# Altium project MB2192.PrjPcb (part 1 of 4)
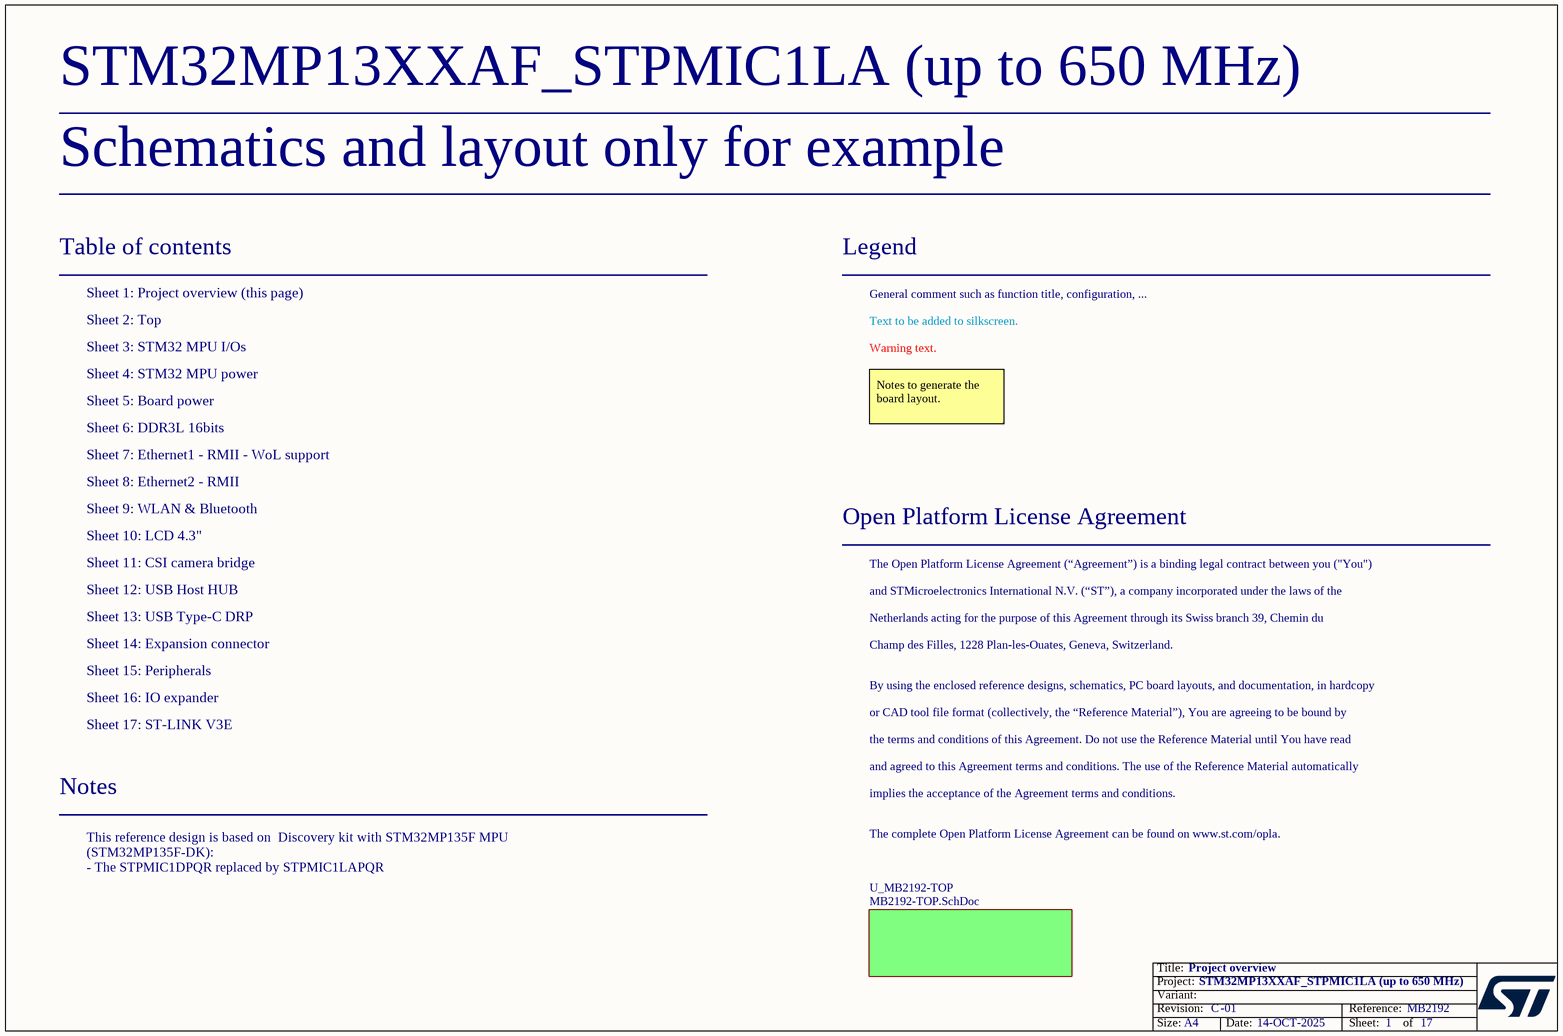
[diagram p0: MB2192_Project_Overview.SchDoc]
Board_Assembly_Revision: 01; Board_Document_Date: 14-OCT-2025; Board_Name: STM32MP13XXAF_STPMIC1LA (up to 650 MHz); Board_PCB_Revision: C; Board_Reference: MB2192
17 sheets, 567 parts. Net scope: flat (ports and power ports of the same name join across sheets).
Board file: MB2192.PcbDoc
Sheets:
  MB2192_Project_Overview.SchDoc
    U_MB2192-TOP = MB2192-TOP.SchDoc
      U_Ethernet1 = Ethernet1_RMII.SchDoc
      U_Ethernet2 = Ethernet2_RMII.SchDoc
      U_Power_MPU = Power_MPU.SchDoc
      U_Power_Board = Power_Board.SchDoc
      U_ST_LINK_V3E = ST-Link_V3E.SchDoc
      U_WLAN_BLUETOOTH = WLAN_BLUETOOTH.SchDoc
      U_Expansion_Connector = Expansion_Connector.SchDoc
      U_Peripherals = Peripherals.SchDoc
      U_MP135_11x11 = MP135_11x11.SchDoc
      U_LTDC = LCD4.3.SchDoc
      U_IO_Expander = MCP_IO_expander.SchDoc
      U_USB_Host = USB_Host_Hub.SchDoc
      U_CSI_DCMI = CSI_Camera_Bridge.SchDoc
      U_DDR = DDR3L_16bits.SchDoc
      U_USB_TypeC_DRP = USB_TypeC_DRP.SchDoc

## Sheet MB2192_Project_Overview.SchDoc: Project overview
size A4; Date: Not used; ApprovedBy: Not used; CheckedBy: Not used; Author: Not used; CompanyName: STMicroelectronics; DrawnBy: Not used; Engineer: Not used; Organization: Not used; Address1: Not used; Address2: Not used; Address3: Not used; Address4: Not used; DocumentNumber: 1; Revision: Not used; SheetNumber: 1; SheetTotal: 17

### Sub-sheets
U_MB2192-TOP = MB2192-TOP.SchDoc: no entries

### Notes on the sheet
- Schematics and layout only for example
- Table of contents
- Sheet 1: Project overview (this page)
- Legend
- General comment such as function title, configuration, ...
- Sheet 2: Top
- Sheet 3: STM32 MPU I/Os
- Sheet 4: STM32 MPU power
- Text to be added to silkscreen.
- Warning text.
- Sheet 6: DDR3L 16bits
- Sheet 5: Board power
- Notes to generate the board layout.
- Sheet 7: Ethernet1 - RMII - WoL support
- Sheet 8: Ethernet2 - RMII
- Sheet 9: WLAN & Bluetooth
- Sheet 10: LCD 4.3"
- Sheet 11: CSI camera bridge
- Open Platform License Agreement
- The Open Platform License Agreement (“Agreement”) is a binding legal contract between you ("You")
- Sheet 13: USB Type-C DRP
- Sheet 12: USB Host HUB
- Sheet 14: Expansion connector
- and STMicroelectronics International N.V. (“ST”), a company incorporated under the laws of the
- Netherlands acting for the purpose of this Agreement through its Swiss branch 39, Chemin du
- Champ des Filles, 1228 Plan-les-Ouates, Geneva, Switzerland.
- Sheet 15: Peripherals
- Sheet 16: IO expander
- By using the enclosed reference designs, schematics, PC board layouts, and documentation, in hardcopy
- or CAD tool file format (collectively, the “Reference Material”), You are agreeing to be bound by
- Sheet 17: ST-LINK V3E
- the terms and conditions of this Agreement. Do not use the Reference Material until You have read
- and agreed to this Agreement terms and conditions. The use of the Reference Material automatically
- Notes
- implies the acceptance of the Agreement terms and conditions.
- The complete Open Platform License Agreement can be found on www.st.com/opla.
- This reference design is based on  Discovery kit with STM32MP135F MPU (STM32MP135F-DK):
  - The STPMIC1DPQR replaced by STPMIC1LAPQR
  - It is applicable to STM32MP13xA and STM32MP13xC (CPU freq up to 650 MHz)

## Sheet MB2192-TOP.SchDoc: TOP
size A3; Date: Not used; ApprovedBy: Not used; CheckedBy: Not used; Author: Not used; CompanyName: STMicroelectronics; DrawnBy: Not used; Engineer: Not used; Organization: Not used; Address1: Not used; Address2: Not used; Address3: Not used; Address4: Not used; DocumentNumber: 2; Revision: Not used; SheetNumber: 2; SheetTotal: 17
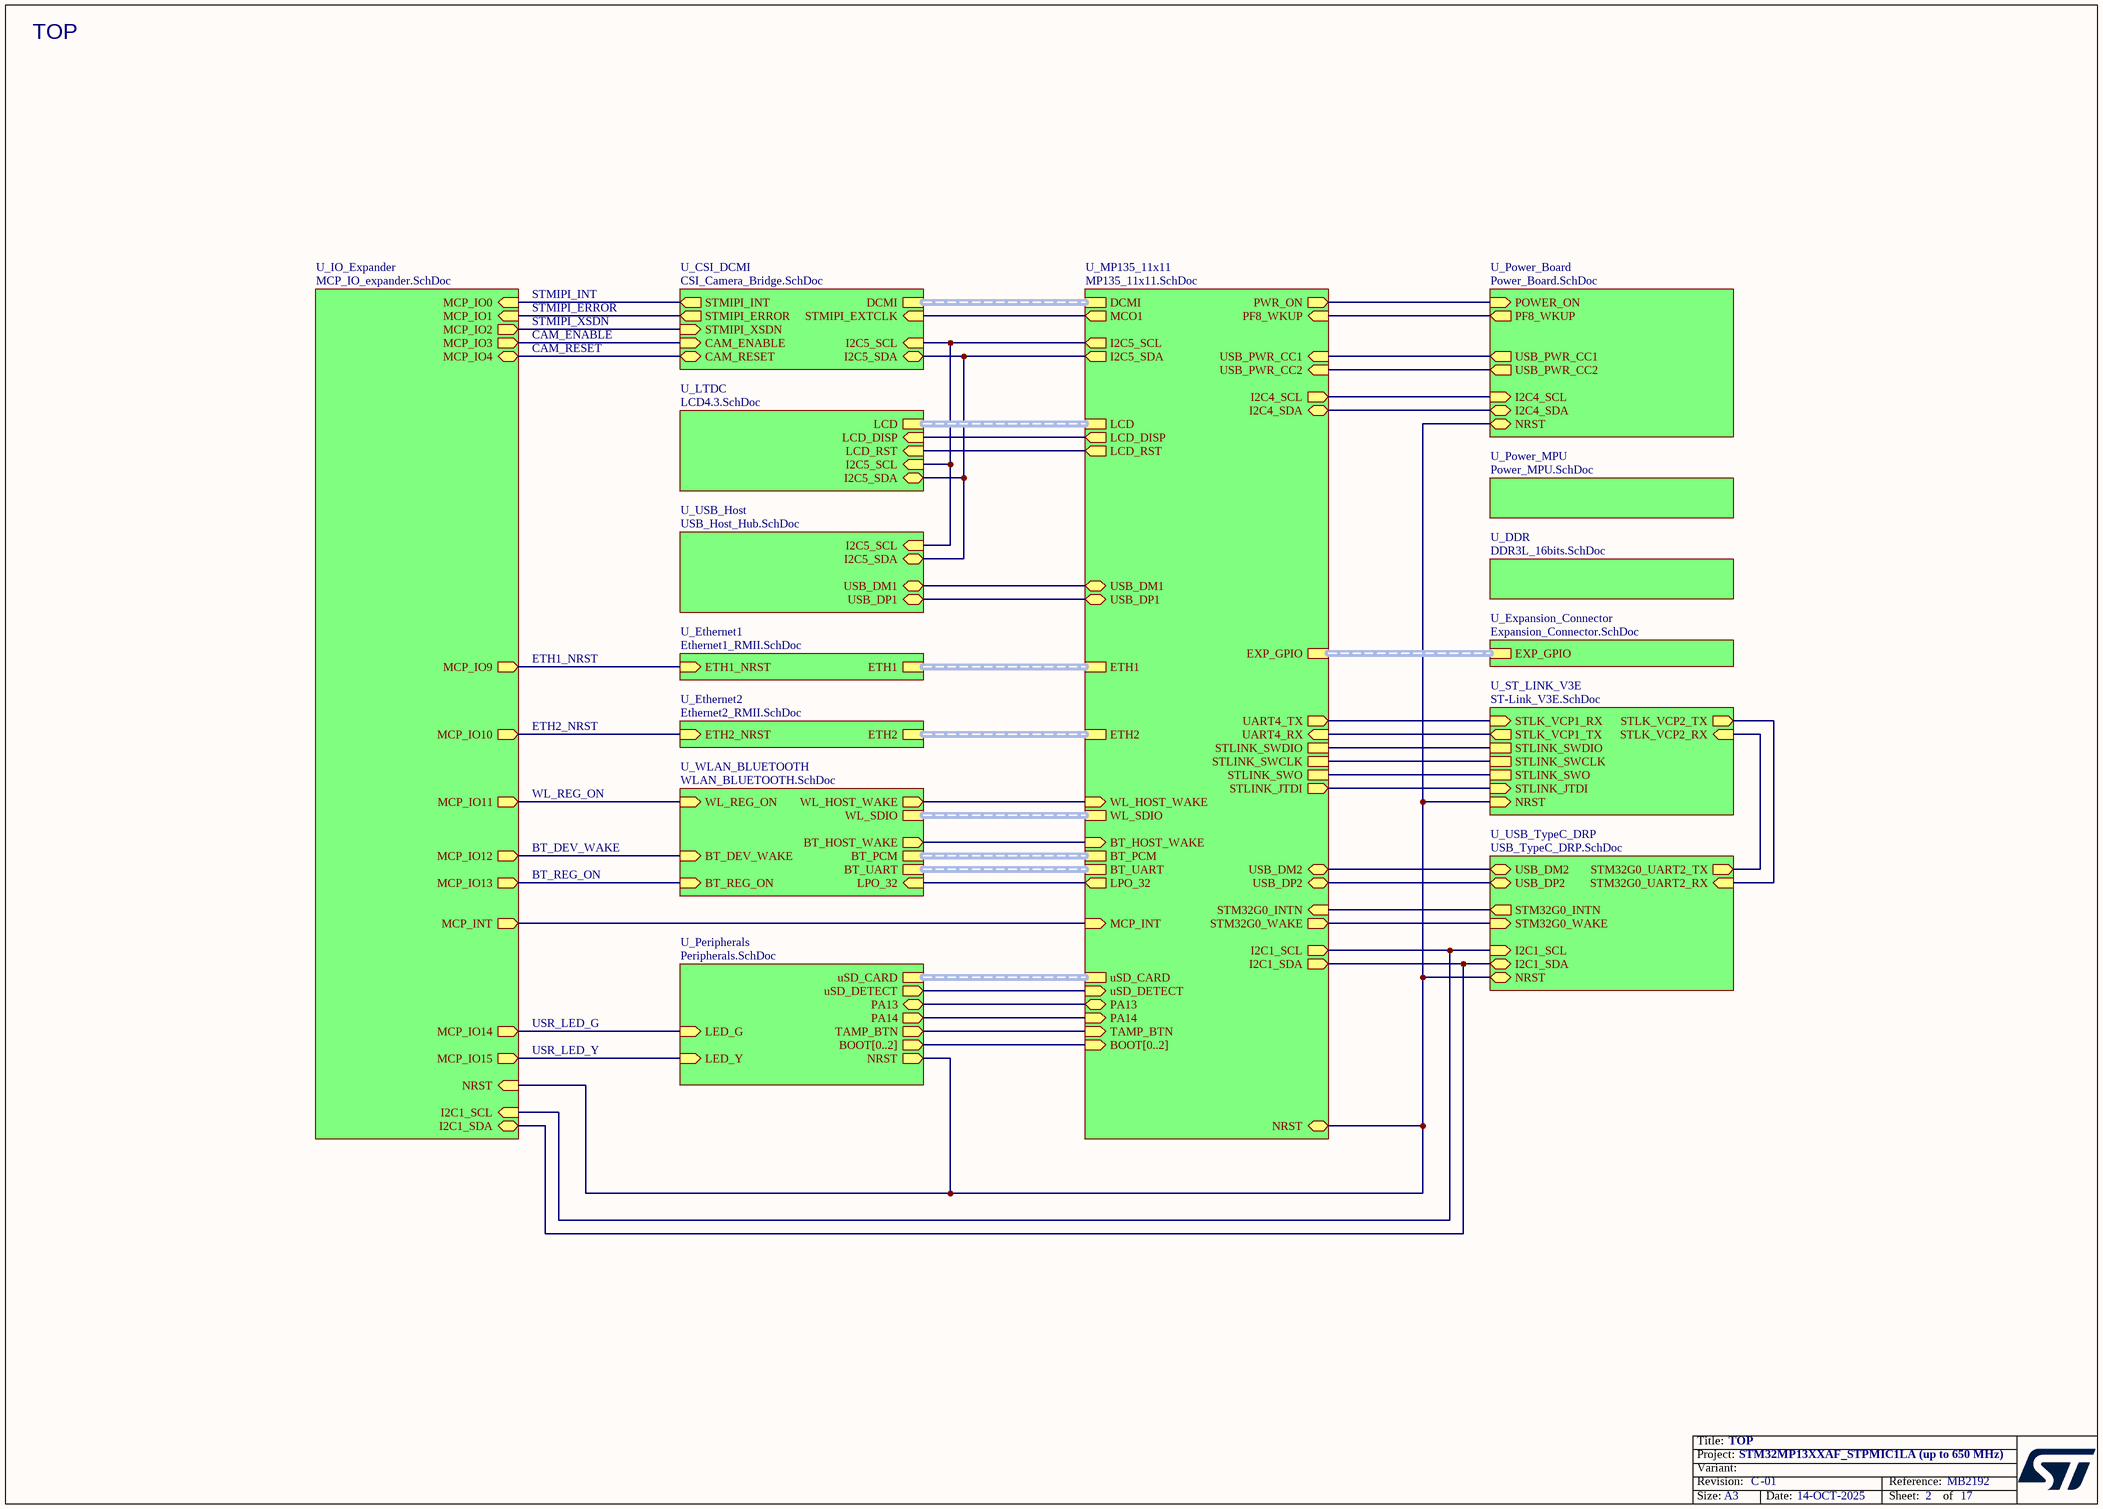
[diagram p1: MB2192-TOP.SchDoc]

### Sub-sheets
U_CSI_DCMI = CSI_Camera_Bridge.SchDoc: DCMI (harness DCMI), I2C5_SCL (in), I2C5_SDA (bidir), STMIPI_EXTCLK (in), STMIPI_ERROR (out), STMIPI_INT (out), CAM_ENABLE (in), CAM_RESET (bidir), STMIPI_XSDN (in)
U_DDR = DDR3L_16bits.SchDoc: no entries
U_Ethernet1 = Ethernet1_RMII.SchDoc: ETH1 (harness ETH1), ETH1_NRST (in)
U_Ethernet2 = Ethernet2_RMII.SchDoc: ETH2 (harness ETH2), ETH2_NRST (in)
U_Expansion_Connector = Expansion_Connector.SchDoc: EXP_GPIO (harness EXP_GPIO)
U_IO_Expander = MCP_IO_expander.SchDoc: MCP_IO1 (in), MCP_IO0 (in), MCP_IO9 (out), MCP_IO10 (out), MCP_IO11 (out), MCP_IO12 (out), MCP_IO13 (out), MCP_IO14 (out), MCP_IO15 (out), I2C1_SCL (in), I2C1_SDA (bidir), MCP_INT (out), NRST (in), MCP_IO3 (out), MCP_IO4 (bidir), MCP_IO2 (out)
U_LTDC = LCD4.3.SchDoc: LCD (harness LCD), I2C5_SCL (in), I2C5_SDA (bidir), LCD_DISP (in), LCD_RST (in)
U_MP135_11x11 = MP135_11x11.SchDoc: uSD_CARD (harness uSD_CARD), PF8_WKUP (in), NRST (bidir), PWR_ON (out), ETH2 (harness ETH2), ETH1 (harness ETH1), I2C1_SCL (out), I2C1_SDA (out), I2C4_SCL (out), I2C4_SDA (bidir), UART4_TX (out), UART4_RX (in), LCD (harness LCD), WL_SDIO (harness WL_SDIO), BOOT[0..2] (in), WL_HOST_WAKE (in), BT_HOST_WAKE (in), LPO_32 (out), BT_PCM (harness BT_PCM), BT_UART (harness BT_UART), DCMI (harness DCMI), EXP_GPIO (harness EXP_GPIO), USB_DM1 (bidir), USB_DM2 (bidir), USB_DP1 (bidir), USB_DP2 (bidir), MCO1 (out), USB_PWR_CC1 (in), USB_PWR_CC2 (in), STLINK_SWDIO, STLINK_SWCLK, STLINK_SWO, PA14 (in), PA13 (bidir), STM32G0_INTN (in), STM32G0_WAKE (out), MCP_INT (in), TAMP_BTN (in), uSD_DETECT (in), LCD_DISP (out), LCD_RST (out), I2C5_SCL (out), I2C5_SDA (out), STLINK_JTDI (out)
U_Peripherals = Peripherals.SchDoc: NRST (out), BOOT[0..2] (out), uSD_CARD (harness uSD_CARD), PA13 (bidir), PA14 (out), LED_Y (in), LED_G (in), uSD_DETECT (out), TAMP_BTN (out)
U_Power_Board = Power_Board.SchDoc: I2C4_SDA (bidir), I2C4_SCL (in), PF8_WKUP (out), NRST (bidir), POWER_ON (in), USB_PWR_CC1 (out), USB_PWR_CC2 (out)
U_Power_MPU = Power_MPU.SchDoc: no entries
U_ST_LINK_V3E = ST-Link_V3E.SchDoc: STLINK_SWDIO, STLINK_SWCLK, STLINK_SWO, STLK_VCP1_RX (in), STLK_VCP1_TX (out), STLK_VCP2_TX (out), STLK_VCP2_RX (in), NRST (in), STLINK_JTDI (in)
U_USB_Host = USB_Host_Hub.SchDoc: USB_DM1 (bidir), USB_DP1 (bidir), I2C5_SDA (bidir), I2C5_SCL (in)
U_USB_TypeC_DRP = USB_TypeC_DRP.SchDoc: USB_DM2 (bidir), USB_DP2 (bidir), I2C1_SCL (in), I2C1_SDA (bidir), STM32G0_INTN (out), STM32G0_WAKE (in), STM32G0_UART2_TX (out), STM32G0_UART2_RX (in), NRST (bidir)
U_WLAN_BLUETOOTH = WLAN_BLUETOOTH.SchDoc: BT_PCM (harness BT_PCM), BT_UART (harness BT_UART), WL_SDIO (harness WL_SDIO), BT_REG_ON (in), BT_HOST_WAKE (out), BT_DEV_WAKE (in), WL_REG_ON (in), WL_HOST_WAKE (out), LPO_32 (in)

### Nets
(unnamed): sheet U_Ethernet1/ETH1_NRST, sheet U_IO_Expander/MCP_IO9
(unnamed): sheet U_Ethernet2/ETH2_NRST, sheet U_IO_Expander/MCP_IO10  [a separate net that carries the same name]
(unnamed): sheet U_Power_Board/I2C4_SDA, sheet U_MP135_11x11/I2C4_SDA  [a separate net that carries the same name]
(unnamed): sheet U_Power_Board/I2C4_SCL, sheet U_MP135_11x11/I2C4_SCL  [a separate net that carries the same name]
(unnamed): sheet U_Power_Board/PF8_WKUP, sheet U_MP135_11x11/PF8_WKUP  [a separate net that carries the same name]
(unnamed): sheet U_Power_Board/NRST, sheet U_ST_LINK_V3E/NRST, sheet U_Peripherals/NRST, sheet U_MP135_11x11/NRST, sheet U_IO_Expander/NRST, sheet U_USB_TypeC_DRP/NRST  [a separate net that carries the same name]
(unnamed): sheet U_Power_Board/POWER_ON, sheet U_MP135_11x11/PWR_ON  [a separate net that carries the same name]
(unnamed): sheet U_Power_Board/USB_PWR_CC1, sheet U_MP135_11x11/USB_PWR_CC1  [a separate net that carries the same name]
(unnamed): sheet U_Power_Board/USB_PWR_CC2, sheet U_MP135_11x11/USB_PWR_CC2  [a separate net that carries the same name]
(unnamed): sheet U_ST_LINK_V3E/STLINK_SWDIO, sheet U_MP135_11x11/STLINK_SWDIO  [a separate net that carries the same name]
(unnamed): sheet U_ST_LINK_V3E/STLINK_SWCLK, sheet U_MP135_11x11/STLINK_SWCLK  [a separate net that carries the same name]
(unnamed): sheet U_ST_LINK_V3E/STLINK_SWO, sheet U_MP135_11x11/STLINK_SWO  [a separate net that carries the same name]
(unnamed): sheet U_ST_LINK_V3E/STLK_VCP1_RX, sheet U_MP135_11x11/UART4_TX  [a separate net that carries the same name]
(unnamed): sheet U_ST_LINK_V3E/STLK_VCP1_TX, sheet U_MP135_11x11/UART4_RX  [a separate net that carries the same name]
(unnamed): sheet U_ST_LINK_V3E/STLK_VCP2_TX, sheet U_USB_TypeC_DRP/STM32G0_UART2_RX  [a separate net that carries the same name]
(unnamed): sheet U_ST_LINK_V3E/STLK_VCP2_RX, sheet U_USB_TypeC_DRP/STM32G0_UART2_TX  [a separate net that carries the same name]
(unnamed): sheet U_ST_LINK_V3E/STLINK_JTDI, sheet U_MP135_11x11/STLINK_JTDI  [a separate net that carries the same name]
(unnamed): sheet U_WLAN_BLUETOOTH/BT_REG_ON, sheet U_IO_Expander/MCP_IO13  [a separate net that carries the same name]
(unnamed): sheet U_WLAN_BLUETOOTH/BT_HOST_WAKE, sheet U_MP135_11x11/BT_HOST_WAKE  [a separate net that carries the same name]
(unnamed): sheet U_WLAN_BLUETOOTH/BT_DEV_WAKE, sheet U_IO_Expander/MCP_IO12  [a separate net that carries the same name]
(unnamed): sheet U_WLAN_BLUETOOTH/WL_REG_ON, sheet U_IO_Expander/MCP_IO11  [a separate net that carries the same name]
(unnamed): sheet U_WLAN_BLUETOOTH/WL_HOST_WAKE, sheet U_MP135_11x11/WL_HOST_WAKE  [a separate net that carries the same name]
(unnamed): sheet U_WLAN_BLUETOOTH/LPO_32, sheet U_MP135_11x11/LPO_32  [a separate net that carries the same name]
(unnamed): sheet U_Peripherals/PA13, sheet U_MP135_11x11/PA13  [a separate net that carries the same name]
(unnamed): sheet U_Peripherals/PA14, sheet U_MP135_11x11/PA14  [a separate net that carries the same name]
(unnamed): sheet U_Peripherals/LED_Y, sheet U_IO_Expander/MCP_IO15  [a separate net that carries the same name]
(unnamed): sheet U_Peripherals/LED_G, sheet U_IO_Expander/MCP_IO14  [a separate net that carries the same name]
(unnamed): sheet U_Peripherals/uSD_DETECT, sheet U_MP135_11x11/uSD_DETECT  [a separate net that carries the same name]
(unnamed): sheet U_Peripherals/TAMP_BTN, sheet U_MP135_11x11/TAMP_BTN  [a separate net that carries the same name]
(unnamed): sheet U_MP135_11x11/I2C1_SCL, sheet U_IO_Expander/I2C1_SCL, sheet U_USB_TypeC_DRP/I2C1_SCL  [a separate net that carries the same name]
(unnamed): sheet U_MP135_11x11/I2C1_SDA, sheet U_IO_Expander/I2C1_SDA, sheet U_USB_TypeC_DRP/I2C1_SDA  [a separate net that carries the same name]
(unnamed): sheet U_MP135_11x11/USB_DM1, sheet U_USB_Host/USB_DM1  [a separate net that carries the same name]
(unnamed): sheet U_MP135_11x11/USB_DM2, sheet U_USB_TypeC_DRP/USB_DM2  [a separate net that carries the same name]
(unnamed): sheet U_MP135_11x11/USB_DP1, sheet U_USB_Host/USB_DP1  [a separate net that carries the same name]
(unnamed): sheet U_MP135_11x11/USB_DP2, sheet U_USB_TypeC_DRP/USB_DP2  [a separate net that carries the same name]
(unnamed): sheet U_MP135_11x11/MCO1, sheet U_CSI_DCMI/STMIPI_EXTCLK  [a separate net that carries the same name]
(unnamed): sheet U_MP135_11x11/STM32G0_INTN, sheet U_USB_TypeC_DRP/STM32G0_INTN  [a separate net that carries the same name]
(unnamed): sheet U_MP135_11x11/STM32G0_WAKE, sheet U_USB_TypeC_DRP/STM32G0_WAKE  [a separate net that carries the same name]
(unnamed): sheet U_MP135_11x11/MCP_INT, sheet U_IO_Expander/MCP_INT  [a separate net that carries the same name]
(unnamed): sheet U_MP135_11x11/LCD_DISP, sheet U_LTDC/LCD_DISP  [a separate net that carries the same name]
(unnamed): sheet U_MP135_11x11/LCD_RST, sheet U_LTDC/LCD_RST  [a separate net that carries the same name]
(unnamed): sheet U_MP135_11x11/I2C5_SCL, sheet U_LTDC/I2C5_SCL, sheet U_USB_Host/I2C5_SCL, sheet U_CSI_DCMI/I2C5_SCL  [a separate net that carries the same name]
(unnamed): sheet U_MP135_11x11/I2C5_SDA, sheet U_LTDC/I2C5_SDA, sheet U_USB_Host/I2C5_SDA, sheet U_CSI_DCMI/I2C5_SDA  [a separate net that carries the same name]
(unnamed): sheet U_IO_Expander/MCP_IO1, sheet U_CSI_DCMI/STMIPI_ERROR  [a separate net that carries the same name]
(unnamed): sheet U_IO_Expander/MCP_IO0, sheet U_CSI_DCMI/STMIPI_INT  [a separate net that carries the same name]
(unnamed): sheet U_IO_Expander/MCP_IO3, sheet U_CSI_DCMI/CAM_ENABLE  [a separate net that carries the same name]
(unnamed): sheet U_IO_Expander/MCP_IO4, sheet U_CSI_DCMI/CAM_RESET  [a separate net that carries the same name]
(unnamed): sheet U_IO_Expander/MCP_IO2, sheet U_CSI_DCMI/STMIPI_XSDN  [a separate net that carries the same name]

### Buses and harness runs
bus sheet U_MP135_11x11/BOOT[0..2] = sheet U_Peripherals/BOOT[0..2]
harness sheet U_CSI_DCMI/DCMI = sheet U_MP135_11x11/DCMI
harness sheet U_Ethernet1/ETH1 = sheet U_MP135_11x11/ETH1
harness sheet U_Ethernet2/ETH2 = sheet U_MP135_11x11/ETH2
harness sheet U_Expansion_Connector/EXP_GPIO = sheet U_MP135_11x11/EXP_GPIO
harness sheet U_LTDC/LCD = sheet U_MP135_11x11/LCD
harness sheet U_MP135_11x11/BT_PCM = sheet U_WLAN_BLUETOOTH/BT_PCM
harness sheet U_MP135_11x11/BT_UART = sheet U_WLAN_BLUETOOTH/BT_UART
harness sheet U_MP135_11x11/uSD_CARD = sheet U_Peripherals/uSD_CARD
harness sheet U_MP135_11x11/WL_SDIO = sheet U_WLAN_BLUETOOTH/WL_SDIO

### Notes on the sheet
- TOP
- STMIPI_INT
- STMIPI_ERROR
- CAM_RESET
- CAM_ENABLE
- STMIPI_XSDN
- ETH1_NRST
- ETH2_NRST
- BT_DEV_WAKE
- WL_REG_ON
- BT_REG_ON
- USR_LED_Y
- USR_LED_G

## Sheet Ethernet1_RMII.SchDoc: Ethernet1 - RMII - WoL support
size A3; Project: Project name; Date: Not used; ApprovedBy: Not used; CheckedBy: Not used; Author: Not used; CompanyName: STMicroelectronics; DrawnBy: Not used; Engineer: Not used; Organization: Not used; Address1: Not used; Address2: Not used; Address3: Not used; Address4: Not used; DocumentNumber: 7; Revision: Not used; SheetNumber: 7; SheetTotal: 17
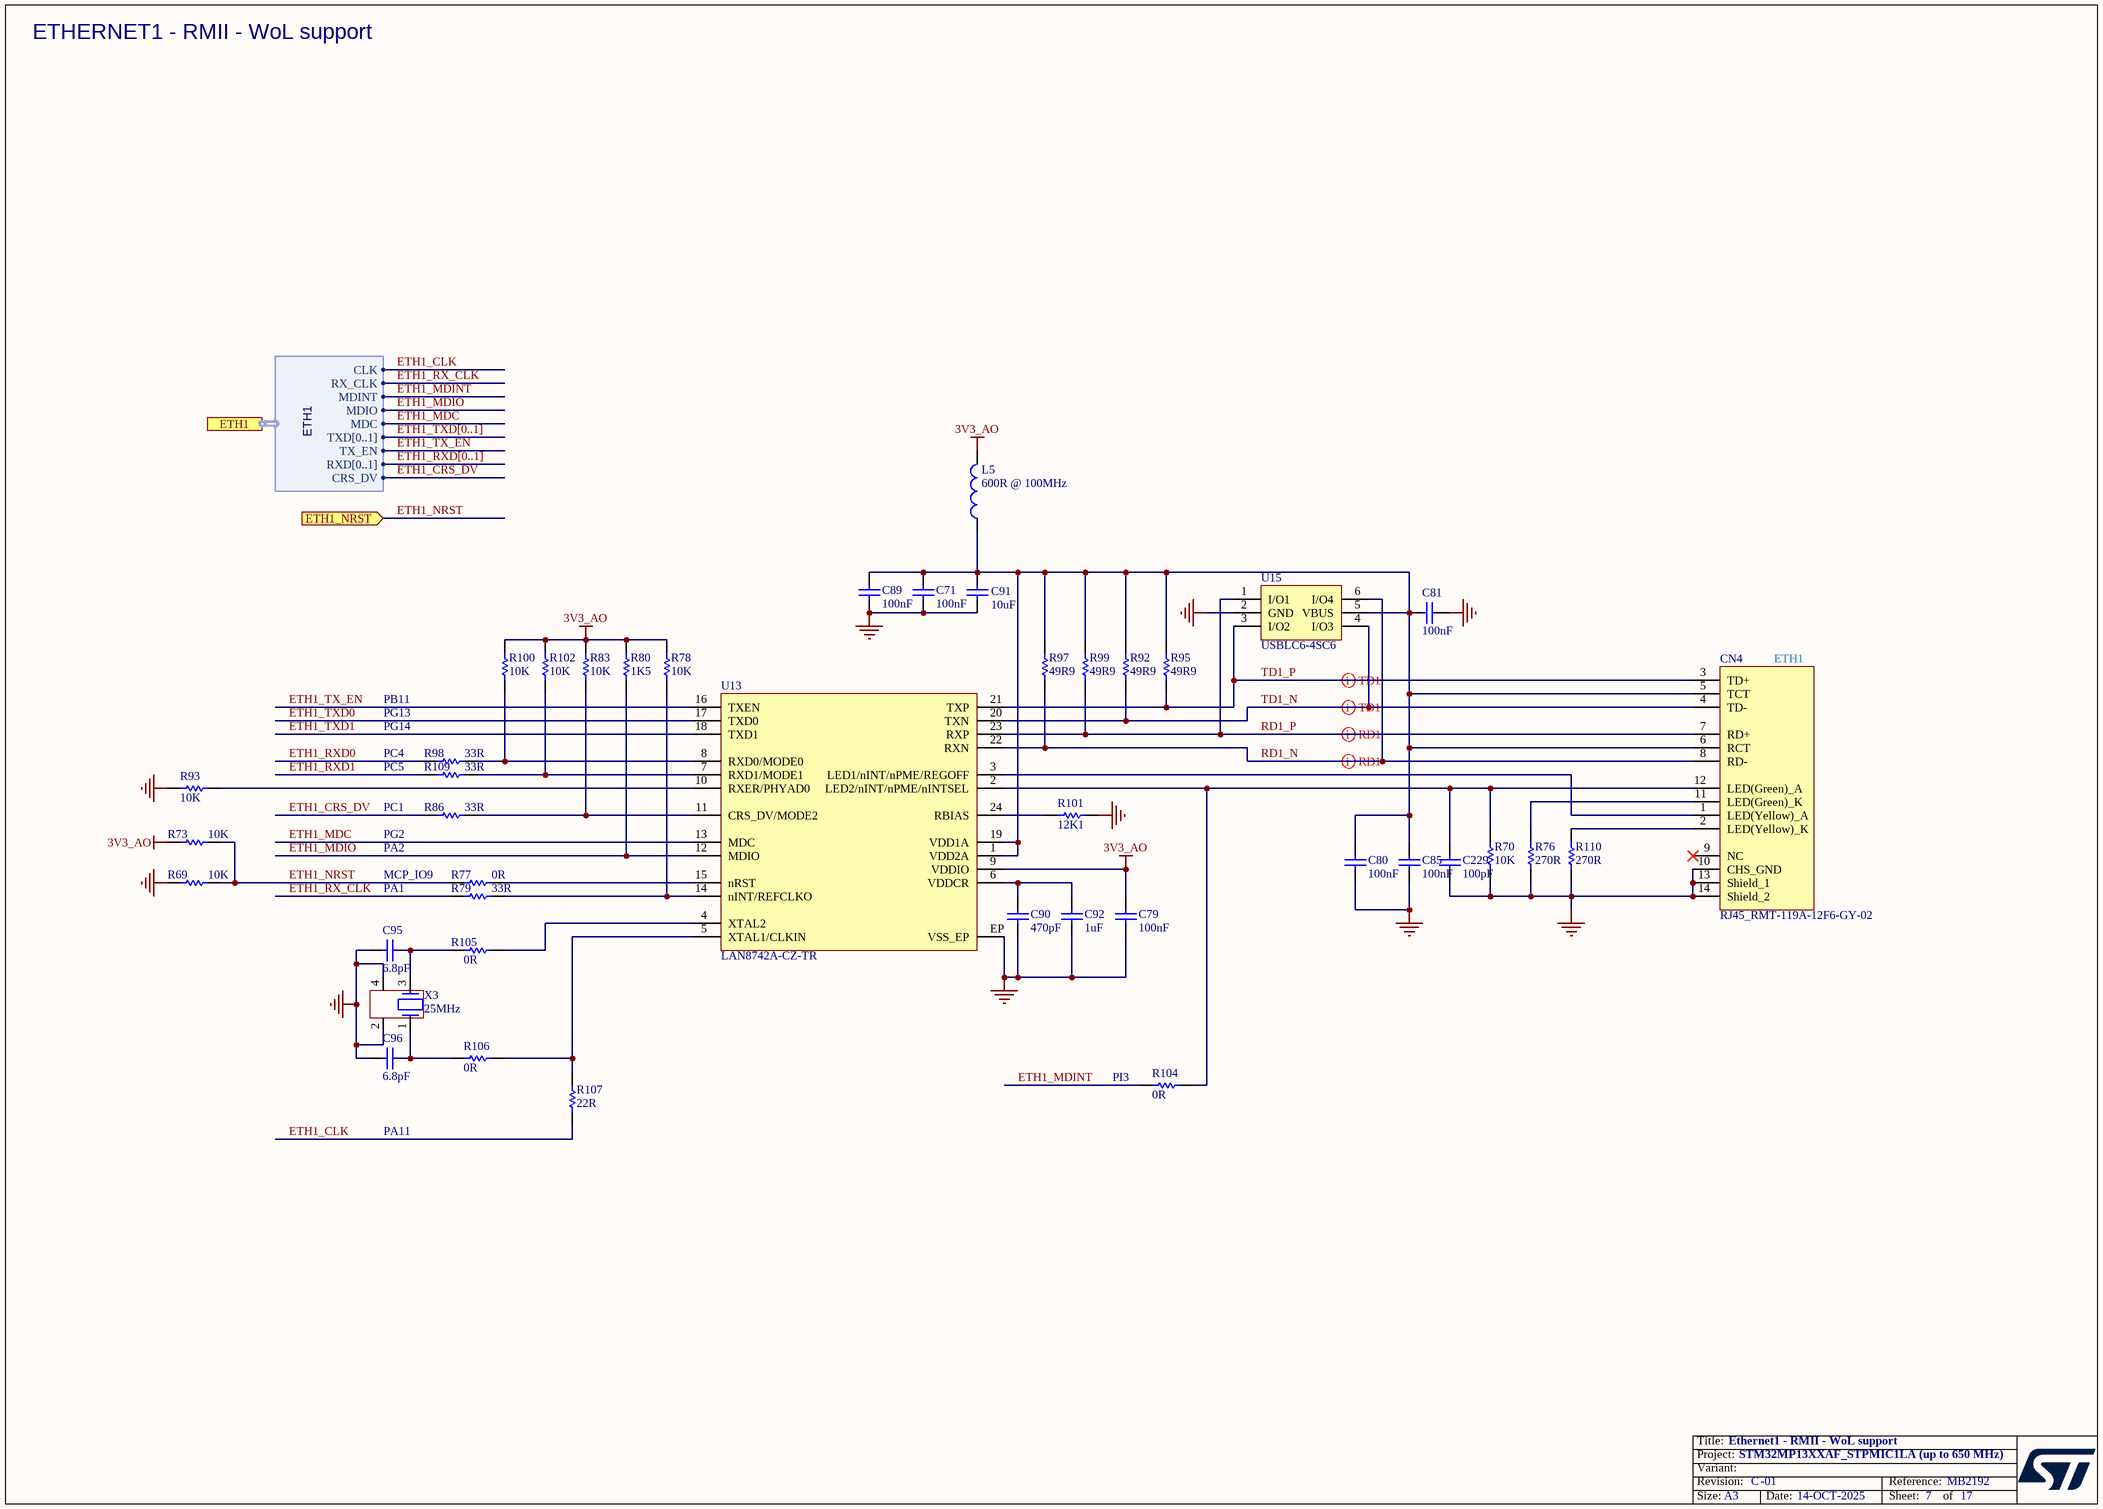
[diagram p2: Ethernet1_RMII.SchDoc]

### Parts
C71  value 100nF  [C0402]  (hidden comment: Capacitor)
C79  value 100nF  [C0402]  (hidden comment: Capacitor)
C80  value 100nF  [C0402]  (hidden comment: Capacitor)
C81  value 100nF  [C0402]  (hidden comment: Capacitor)
C85  value 100nF  [C0402]  (hidden comment: Capacitor)
C89  value 100nF  [C0402]  (hidden comment: Capacitor)
C90  value 470pF  [C0402]  (hidden comment: Capacitor)
C91  value 10uF  [C0603]  (hidden comment: Capacitor)
C92  value 1uF  [C0201_MURATA_GRM033_H0P3]  (hidden comment: Capacitor)
C95  value 6.8pF  [C0402]  (hidden comment: Capacitor)
C96  value 6.8pF  [C0402]  (hidden comment: Capacitor)
C229  value 100pF  [C0402]  (hidden comment: Capacitor)
CN4  value RJ45_RMT-119A-12F6-GY-02  [CON_RJ45_PHC_RMT-119A-12F6-GY-02]  (hidden comment: RJ45_RTS-119A-12F6-GY-02)
L5  value 600R @ 100MHz  [L0603]  (hidden comment: BEAD)
R69  value 10K  [R0402]  (hidden comment: Resistor)
R70  value 10K  [R0402]  (hidden comment: Resistor)
R73  value 10K  [R0402]  (hidden comment: Resistor)
R76  value 270R  [R0402]  (hidden comment: Resistor)
R77  value 0R  [R0402]  (hidden comment: Resistor)
R78  value 10K  [R0402]  (hidden comment: Resistor)
R79  value 33R  [R0402]  (hidden comment: Resistor)
R80  value 1K5  [R0402]  (hidden comment: Resistor)
R83  value 10K  [R0402]  (hidden comment: Resistor)
R86  value 33R  [R0402]  (hidden comment: Resistor)
R92  value 49R9  [R0402]  (hidden comment: Resistor)
R93  value 10K  [R0402]  (hidden comment: Resistor)
R95  value 49R9  [R0402]  (hidden comment: Resistor)
R97  value 49R9  [R0402]  (hidden comment: Resistor)
R98  value 33R  [R0402]  (hidden comment: Resistor)
R99  value 49R9  [R0402]  (hidden comment: Resistor)
R100  value 10K  [R0402]  (hidden comment: Resistor)
R101  value 12K1  [R0402]  (hidden comment: Resistor)
R102  value 10K  [R0402]  (hidden comment: Resistor)
R104  value 0R  [R0402]  (hidden comment: Resistor)
R105  value 0R  [R0402]  (hidden comment: Resistor)
R106  value 0R  [R0402]  (hidden comment: Resistor)
R107  value 22R  [R0402]  (hidden comment: Resistor)
R109  value 33R  [R0402]  (hidden comment: Resistor)
R110  value 270R  [R0402]  (hidden comment: Resistor)
U13  LAN8742A-CZ-TR  [ICC_VQFN24-EPAD_4X4_P050]
U15  USBLC6-4SC6  [ESD_SOT23-6L]
X3  value 25MHz  [CRY_NX2016SA_4P]  (hidden comment: XTAL_4_PINS)

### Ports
ETH1 (harness ETH1), ETH1_NRST (in)

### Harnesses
ETH1: MDINT, TXD[0..1], MDIO, MDC, RX_CLK, TX_EN, RXD[0..1], CRS_DV, CLK

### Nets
3V3_AO: C79.2 L5.2 R73.2 R78.2 R80.2 R83.2 R100.2 R102.2 U13.9(VDDIO)
GND: C71.1 C79.1 C80.1 C81.2 C85.1 C89.1 C90.1 C91.2 C92.1 C95.1 C96.1 C229.1 CN4.10(CHS_GND) CN4.13(Shield_1) CN4.14(Shield_2) R69.2 R70.1 R76.1 R93.2 R101.2 R110.1 U13.EP(VSS_EP) U15.2(GND) X3.2 X3.4
ETH1_CLK: R107.1 ; port ETH1.CLK
ETH1_CRS_DV: R86.1 ; port ETH1.CRS_DV
ETH1_MDC: U13.13(MDC) ; port ETH1.MDC
ETH1_MDINT: R104.1 ; port ETH1.MDINT
ETH1_MDIO: R80.1 U13.12(MDIO) ; port ETH1.MDIO
ETH1_NRST: R69.1 R73.1 R77.1 ; port ETH1_NRST
ETH1_RX_CLK: R79.1 ; port ETH1.RX_CLK
ETH1_RXD0: R98.1
ETH1_RXD1: R109.1
ETH1_TX_EN: U13.16(TXEN) ; port ETH1.TX_EN
ETH1_TXD0: U13.17(TXD0)
ETH1_TXD1: U13.18(TXD1)
RD1_N: CN4.8(RD-) R97.1 U13.22(RXN) U15.6(I/O4)
RD1_P: CN4.7(RD+) R99.1 U13.23(RXP) U15.1(I/O1)
TD1_N: CN4.4(TD-) R92.1 U13.20(TXN) U15.4(I/O3)
TD1_P: CN4.3(TD+) R95.1 U13.21(TXP) U15.3(I/O2)
NetC71_2: C71.2 C80.2 C81.1 C85.2 C89.2 C91.1 CN4.5(TCT) CN4.6(RCT) L5.1 R92.2 R95.2 R97.2 R99.2 U13.1(VDD2A) U13.19(VDD1A) U15.5(VBUS)
NetC90_2: C90.2 C92.2 U13.6(VDDCR)
NetC95_2: C95.2 R105.1 X3.3
NetC96_2: C96.2 R106.1 X3.1
NetC229_2: C229.2 CN4.12(LED(Green)_A) R70.2 R104.2 U13.2(LED2/nINT/nPME/nINTSEL)
NetCN4_1: CN4.1(LED(Yellow)_A) U13.3(LED1/nINT/nPME/REGOFF)
NetCN4_2: CN4.2(LED(Yellow)_K) R110.2
NetCN4_11: CN4.11(LED(Green)_K) R76.2
NetR77_2: R77.2 U13.15(nRST)
NetR78_1: R78.1 R79.2 U13.14(nINT/REFCLKO)
NetR83_1: R83.1 R86.2 U13.11(CRS_DV/MODE2)
NetR93_1: R93.1 U13.10(RXER/PHYAD0)
NetR98_2: R98.2 R100.1 U13.8(RXD0/MODE0)
NetR101_1: R101.1 U13.24(RBIAS)
NetR102_1: R102.1 R109.2 U13.7(RXD1/MODE1)
NetR105_2: R105.2 U13.4(XTAL2)
NetR106_2: R106.2 R107.2 U13.5(XTAL1/CLKIN)

Not connected (* = marked no-connect by the designer): CN4 9(NC)*

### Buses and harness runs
bus ETH1_RXD[0..1]
bus ETH1_TXD[0..1]

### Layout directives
differential pair: RD1_N, RD1_P, TD1_N, TD1_P

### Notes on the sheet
- ETHERNET1 - RMII - WoL support
- PB11
- PG13
- ETH1
- PC4
- PC5
- PG14
- PC1
- (near R86) PG2
- PA2
- PA1
- MCP_IO9
- (near R104) PI3
- PA11

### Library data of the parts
C71 C79-C81 C85 C89 = MCD-00006: Capacitor, MLCC, 100nF, 16V, X7R, +/-10%, 0402, T=0.5mm; Manufacturer_Part_Number: CC0402KRX7R7BB104; Manufacturer: YAGEO; Part_Preference: Recommended; Partial_Alternate_Internal_Part_Number: MCD-03299; Order_Code_RS: 9402047; Component_Country_Of_Origin: China; ShowFields: YES; ID: 2474
C90 = MCD-00724: Capacitor, MLCC, 470pF, 50V, NPO, +/-5%, 0402, T=0.5mm; Manufacturer_Part_Number: CC0402JRNPO9BN471; Manufacturer: YAGEO; Part_Preference: Recommended; Order_Code_RS: 199-2186; Component_Country_Of_Origin: China; ShowFields: YES; ID: 3023
C91 = MCD-00099: Capacitor, MLCC, 10uF, 10V, X5R, +/-10%, 0603, T=0.8mm; Manufacturer_Part_Number: GRM188R61A106KE69; Manufacturer: MURATA; Part_Preference: Recommended; Partial_Alternate_Internal_Part_Number: MCD-03152; Order_Code_RS: 2494233; Component_Country_Of_Origin: Japan°°; ShowFields: YES; ID: 2770
C92 = MCD-02377: Capacitor, MLCC, 1uF, 6.3V, X5R, +/-20%, 0201, T=0,3mm; Manufacturer_Part_Number: GRM033R60J105MEA2; Manufacturer: MURATA; Part_Preference: Recommended; Partial_Alternate_Internal_Part_Number: MCD-04356; Order_Code_RS: 820-0643; Component_Country_Of_Origin: Japan°; ShowFields: YES; ID: 4483
C95 C96 = MCD-00674: Capacitor, MLCC, 6.8pF, 50V, NPO, +/-0.25pF, 0402, T=0.5mm; Manufacturer_Part_Number: CC0402CRNPO9BN6R8; Manufacturer: YAGEO; Part_Preference: Recommended; Component_Country_Of_Origin: China; ShowFields: YES; ID: 3068
C229 = MCD-00205: Capacitor, MLCC, 100pF, 50V, NPO, +/-5%, 0402, T=0.5mm; Manufacturer_Part_Number: CC0402JRNPO9BN101; Manufacturer: YAGEO; Part_Preference: Recommended; Component_Country_Of_Origin: China; ShowFields: YES; ID: 2658
CN4 = MCD-02475: connector_RJ45, 10/100 Ethernet integrated MAG with integrate Green and Yellow LED, T= 13.61mm; Part_Preference: Recommended; Manufacturer: PENGHUI; Manufacturer_Part_Number: RMT-119A-12F6-GY-02; ShowFields: YES; ID: 4581; Component_Country_Of_Origin: China
L5 = MCD-00047: Ferrite bead, 600R @1 00MHz, +/-25%, 350mA, 0R5, 0603, T=0.8mm; Part_Type: Inductor; Manufacturer_Part_Number: FCM1608KF-601T03; Manufacturer: TAI-TECH; Part_Preference: Recommended; Partial_Alternate_Internal_Part_Number: MCD-02959; Component_Country_Of_Origin: Unknown; ShowFields: YES; ID: 2546
R69 R73 = MCD-00053: Resistor, 10K, 0402, +/-1%, 1/16W; Manufacturer_Part_Number: RC0402FR-0710KL; Manufacturer: YAGEO; Part_Preference: Recommended; BMS_Part_Number: 9131590; Order_Code_RS: 9239359; Component_Country_Of_Origin: China; ShowFields: YES; ID: 2539
R70 R78 R83 R93 R100 R102 = MCD-00053: Resistor, 10K, 0402, +/-1%, 1/16W; Manufacturer_Part_Number: RC0402FR-0710KL; Manufacturer: YAGEO; BMS_Part_Number: 9131590; Part_Preference: Recommended; Order_Code_RS: 9239359; Component_Country_Of_Origin: China; ShowFields: YES; ID: 2539
R76 R110 = MCD-00441: Resistor, 270R, 0402, +/-1%, 1/16W; Manufacturer_Part_Number: RC0402FR-07270RL; Manufacturer: YAGEO; Part_Preference: Recommended; Component_Country_Of_Origin: China; ShowFields: YES; ID: 2838
R77 = MCD-00052: Resistor, 0R, 0402, +/-5%, 1/16W; Part_Preference: Recommended; Manufacturer: YAGEO; Manufacturer_Part_Number: RC0402JR-070RL; Order_Code_RS: 9232516RL; Component_Country_Of_Origin: China; ShowFields: YES; ID: 2540
R79 R86 R98 R109 = MCD-00455: Resistor, 33R, 0402, +/-1%, 1/16W; Manufacturer_Part_Number: RC0402FR-0733RL; Manufacturer: YAGEO; Part_Preference: Recommended; Component_Country_Of_Origin: China; ShowFields: YES; ID: 2821
R80 = MCD-00068: Resistor, 1K5, 0402, +/-1%, 1/16W; Manufacturer_Part_Number: RC0402FR-071K5L; Manufacturer: YAGEO; Part_Preference: Recommended; Order_Code_RS: 9239251; Component_Country_Of_Origin: China; ShowFields: YES; ID: 2524
R92 R95 R97 R99 = MCD-00565: Resistor, 49R9, 0402, +/-1%, 1/16W; Manufacturer_Part_Number: RC0402FR-0749R9L; Manufacturer: YAGEO; Part_Preference: Recommended; Component_Country_Of_Origin: China; ShowFields: YES; ID: 3178
R101 = MCD-00723: Resistor, 12K1, 0402, +/-1%, 1/16W; Manufacturer_Part_Number: RC0402FR-0712K1L; Manufacturer: YAGEO; Part_Preference: Recommended; Component_Country_Of_Origin: China; ShowFields: YES; ID: 3022
R104-R106 = MCD-00052: Resistor, 0R, 0402, +/-5%, 1/16W; Manufacturer_Part_Number: RC0402JR-070RL; Manufacturer: YAGEO; Part_Preference: Recommended; Order_Code_RS: 9232516RL; Component_Country_Of_Origin: China; ShowFields: YES; ID: 2540
R107 = MCD-00189: Resistor, 22R, 0402, +/-1%, 1/16W; Manufacturer_Part_Number: RC0402FR-0722RL; Manufacturer: YAGEO; Part_Preference: Recommended; Component_Country_Of_Origin: China; ShowFields: YES; ID: 2677
U13 = MCD-00719: 10/100M RMII Ethernet transceiver; Part_Type: IC; Manufacturer: MICROCHIP; BMS_Part_Number: 9177984; Part_Preference: Recommended; Partial_Alternate_Internal_Part_Number: MCD-03200; Component_Country_Of_Origin: Unknown; ShowFields: YES; ID: 3026; Order_Code_RS: 215-3925
U15 = MCD-00250: Very low capacitance ESD protection , 4 lines; Part_Type: Diode; Manufacturer: STMICROELECTRONICS; BMS_Part_Number: 9151001; Part_Preference: Recommended; Manufacturer_HQ_COO: EU; Component_Country_Of_Origin: China; ShowFields: YES; ID: 2616; Order_Code_RS: 920-6272
X3 = MCD-01364: Crystal, 25MHz, 6pF, +/-20ppm, 80R, 2x1.6mm; BMS_Part_Number: 9157044; Part_Preference: Recommended; Part_Type: Crystal_Osc; Manufacturer: NDK; Manufacturer_Part_Number: NX2016SA-25MHZ-EXS00A-CS11321; Component_Country_Of_Origin: Japan; ShowFields: YES; ID: 3464

## Sheet Ethernet2_RMII.SchDoc: Ethernet2 - RMII
size A3; Project: Project name; Date: Not used; ApprovedBy: Not used; CheckedBy: Not used; Author: Not used; CompanyName: STMicroelectronics; DrawnBy: Not used; Engineer: Not used; Organization: Not used; Address1: Not used; Address2: Not used; Address3: Not used; Address4: Not used; DocumentNumber: 8; Revision: Not used; SheetNumber: 8; SheetTotal: 17
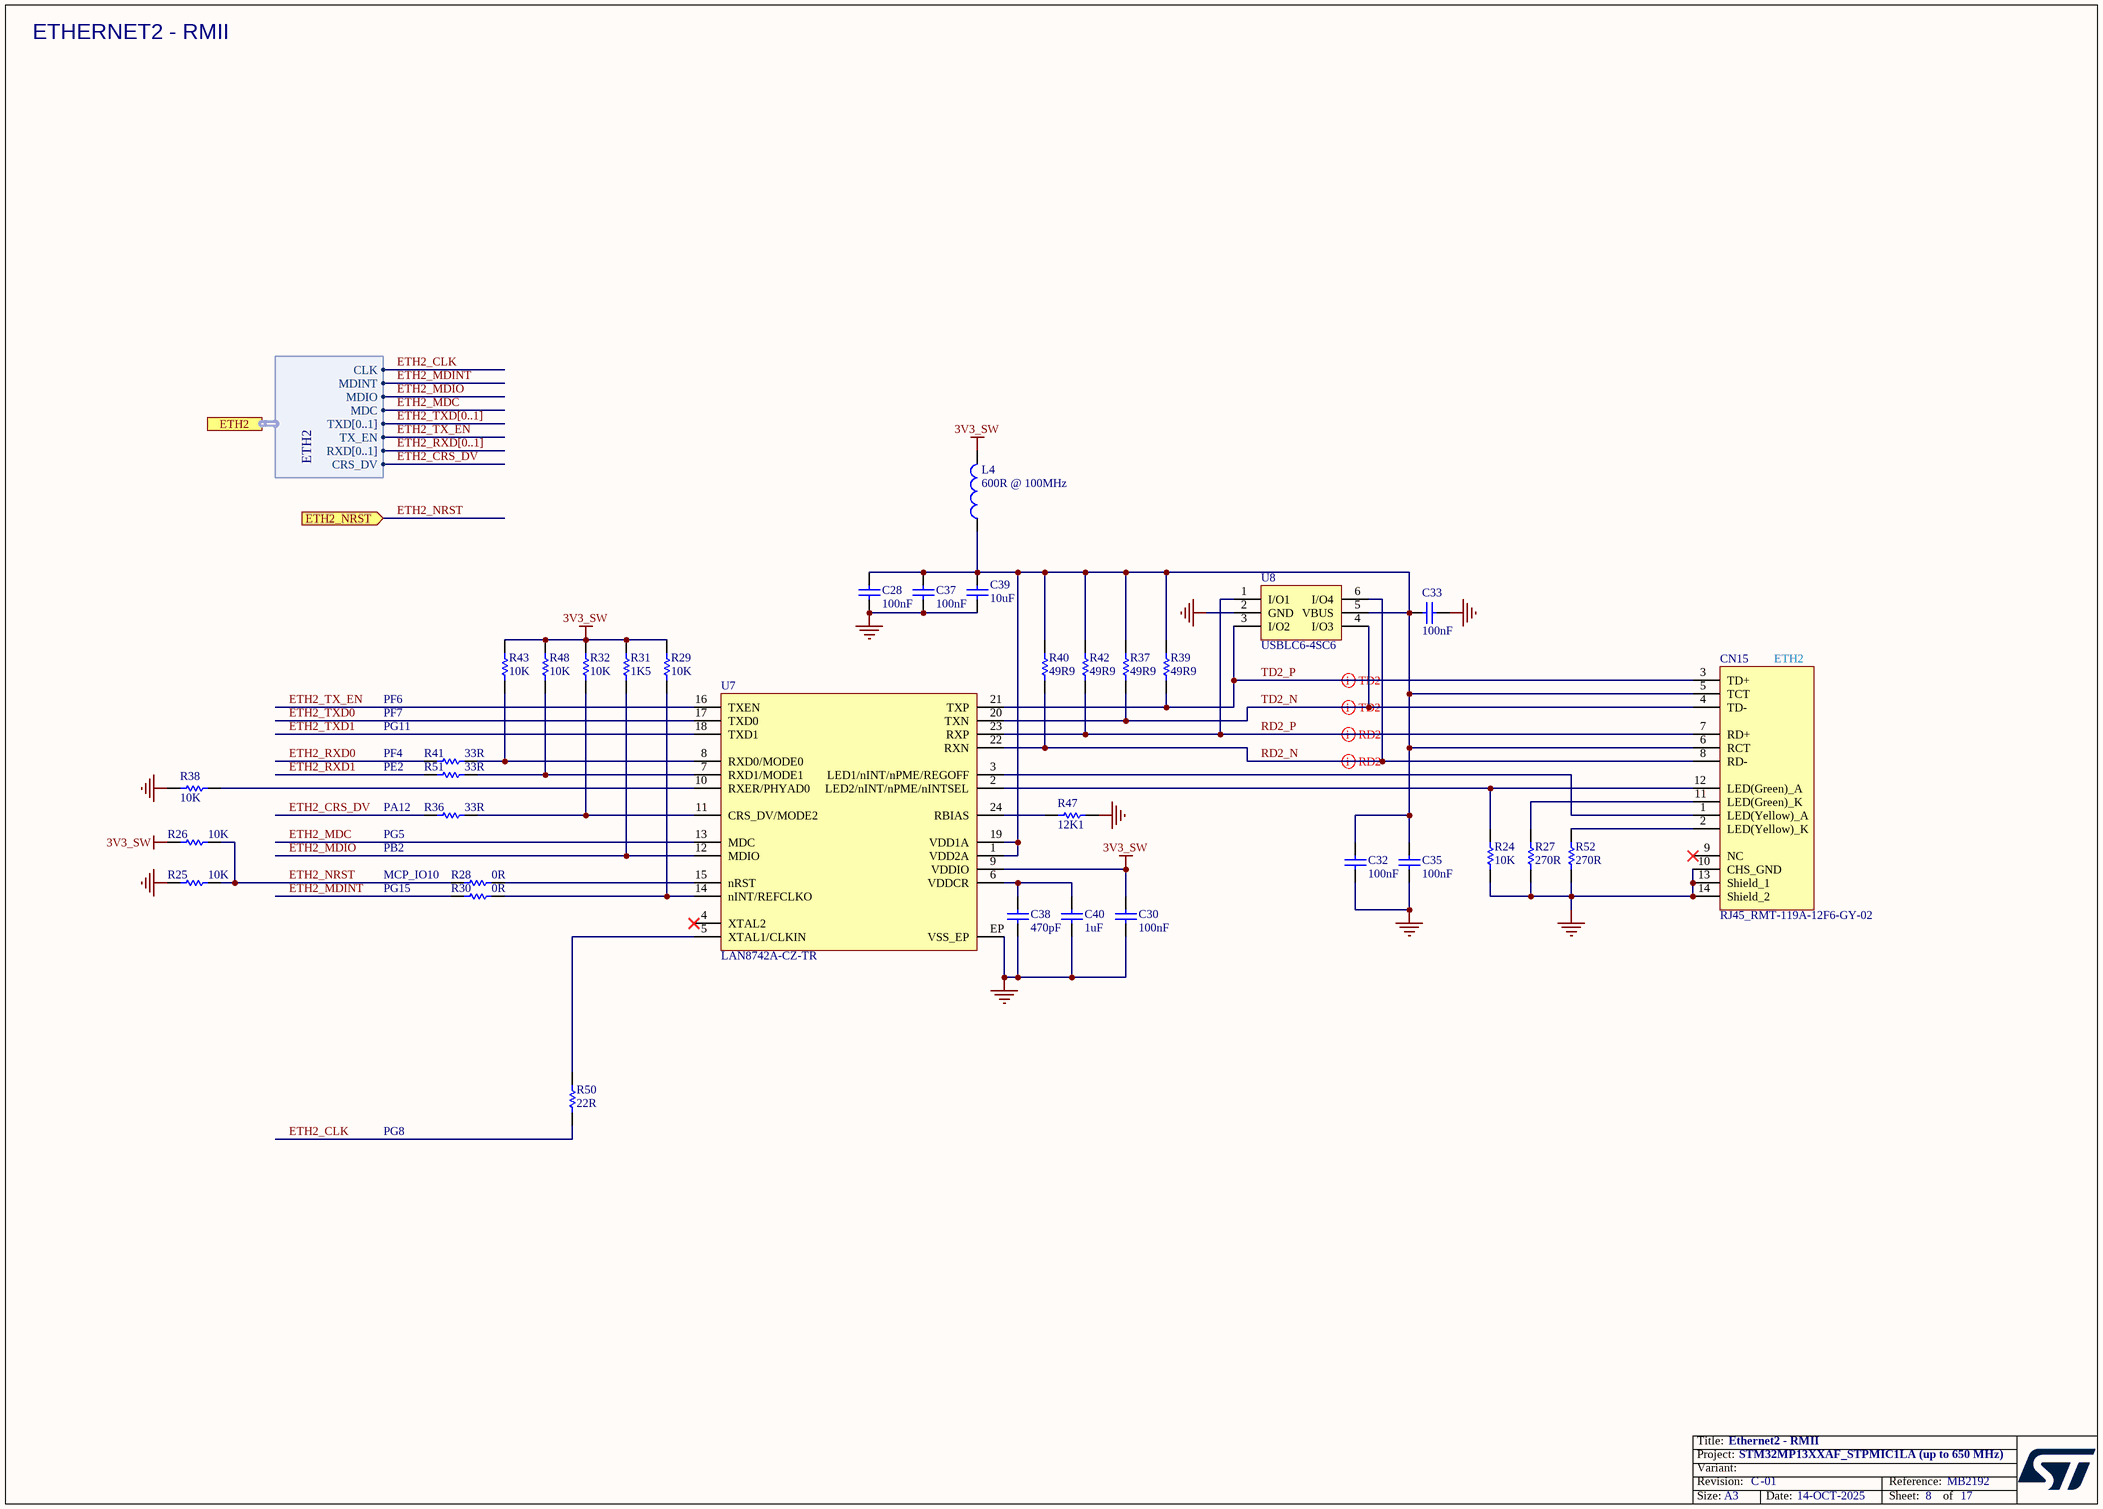
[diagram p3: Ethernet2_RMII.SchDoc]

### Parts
C28  value 100nF  [C0402]  (hidden comment: Capacitor)
C30  value 100nF  [C0402]  (hidden comment: Capacitor)
C32  value 100nF  [C0402]  (hidden comment: Capacitor)
C33  value 100nF  [C0402]  (hidden comment: Capacitor)
C35  value 100nF  [C0402]  (hidden comment: Capacitor)
C37  value 100nF  [C0402]  (hidden comment: Capacitor)
C38  value 470pF  [C0402]  (hidden comment: Capacitor)
C39  value 10uF  [C0603]  (hidden comment: Capacitor)
C40  value 1uF  [C0201_MURATA_GRM033_H0P3]  (hidden comment: Capacitor)
CN15  value RJ45_RMT-119A-12F6-GY-02  [CON_RJ45_PHC_RMT-119A-12F6-GY-02]  (hidden comment: RJ45_RTS-119A-12F6-GY-02)
L4  value 600R @ 100MHz  [L0603]  (hidden comment: BEAD)
R24  value 10K  [R0402]  (hidden comment: Resistor)
R25  value 10K  [R0402]  (hidden comment: Resistor)
R26  value 10K  [R0402]  (hidden comment: Resistor)
R27  value 270R  [R0402]  (hidden comment: Resistor)
R28  value 0R  [R0402]  (hidden comment: Resistor)
R29  value 10K  [R0402]  (hidden comment: Resistor)
R30  value 0R  [R0402]  (hidden comment: Resistor)
R31  value 1K5  [R0402]  (hidden comment: Resistor)
R32  value 10K  [R0402]  (hidden comment: Resistor)
R36  value 33R  [R0402]  (hidden comment: Resistor)
R37  value 49R9  [R0402]  (hidden comment: Resistor)
R38  value 10K  [R0402]  (hidden comment: Resistor)
R39  value 49R9  [R0402]  (hidden comment: Resistor)
R40  value 49R9  [R0402]  (hidden comment: Resistor)
R41  value 33R  [R0402]  (hidden comment: Resistor)
R42  value 49R9  [R0402]  (hidden comment: Resistor)
R43  value 10K  [R0402]  (hidden comment: Resistor)
R47  value 12K1  [R0402]  (hidden comment: Resistor)
R48  value 10K  [R0402]  (hidden comment: Resistor)
R50  value 22R  [R0402]  (hidden comment: Resistor)
R51  value 33R  [R0402]  (hidden comment: Resistor)
R52  value 270R  [R0402]  (hidden comment: Resistor)
U7  LAN8742A-CZ-TR  [ICC_VQFN24-EPAD_4X4_P050]
U8  USBLC6-4SC6  [ESD_SOT23-6L]

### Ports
ETH2 (harness ETH2), ETH2_NRST (in)

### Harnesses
ETH2: MDINT, TXD[0..1], MDIO, MDC, TX_EN, RXD[0..1], CRS_DV, CLK

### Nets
3V3_SW: C30.2 L4.2 R26.2 R29.2 R31.2 R32.2 R43.2 R48.2 U7.9(VDDIO)
GND: C28.1 C30.1 C32.1 C33.2 C35.1 C37.1 C38.1 C39.2 C40.1 CN15.10(CHS_GND) CN15.13(Shield_1) CN15.14(Shield_2) R24.1 R25.2 R27.1 R38.2 R47.2 R52.1 U7.EP(VSS_EP) U8.2(GND)
ETH2_CLK: R50.1 ; port ETH2.CLK
ETH2_CRS_DV: R36.1 ; port ETH2.CRS_DV
ETH2_MDC: U7.13(MDC) ; port ETH2.MDC
ETH2_MDINT: R30.1 ; port ETH2.MDINT
ETH2_MDIO: R31.1 U7.12(MDIO) ; port ETH2.MDIO
ETH2_NRST: R25.1 R26.1 R28.1 ; port ETH2_NRST
ETH2_RXD0: R41.1
ETH2_RXD1: R51.1
ETH2_TX_EN: U7.16(TXEN) ; port ETH2.TX_EN
ETH2_TXD0: U7.17(TXD0)
ETH2_TXD1: U7.18(TXD1)
RD2_N: CN15.8(RD-) R40.1 U7.22(RXN) U8.6(I/O4)
RD2_P: CN15.7(RD+) R42.1 U7.23(RXP) U8.1(I/O1)
TD2_N: CN15.4(TD-) R37.1 U7.20(TXN) U8.4(I/O3)
TD2_P: CN15.3(TD+) R39.1 U7.21(TXP) U8.3(I/O2)
NetC28_2: C28.2 C32.2 C33.1 C35.2 C37.2 C39.1 CN15.5(TCT) CN15.6(RCT) L4.1 R37.2 R39.2 R40.2 R42.2 U7.1(VDD2A) U7.19(VDD1A) U8.5(VBUS)
NetC38_2: C38.2 C40.2 U7.6(VDDCR)
NetCN15_1: CN15.1(LED(Yellow)_A) U7.3(LED1/nINT/nPME/REGOFF)
NetCN15_2: CN15.2(LED(Yellow)_K) R52.2
NetCN15_11: CN15.11(LED(Green)_K) R27.2
NetCN15_12: CN15.12(LED(Green)_A) R24.2 U7.2(LED2/nINT/nPME/nINTSEL)
NetR28_2: R28.2 U7.15(nRST)
NetR29_1: R29.1 R30.2 U7.14(nINT/REFCLKO)
NetR32_1: R32.1 R36.2 U7.11(CRS_DV/MODE2)
NetR38_1: R38.1 U7.10(RXER/PHYAD0)
NetR41_2: R41.2 R43.1 U7.8(RXD0/MODE0)
NetR47_1: R47.1 U7.24(RBIAS)
NetR48_1: R48.1 R51.2 U7.7(RXD1/MODE1)
NetR50_2: R50.2 U7.5(XTAL1/CLKIN)

Not connected (* = marked no-connect by the designer): CN15 9(NC)*; U7 4(XTAL2)*

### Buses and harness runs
bus ETH2_RXD[0..1]
bus ETH2_TXD[0..1]

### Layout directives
differential pair: RD2_N, RD2_P, TD2_N, TD2_P

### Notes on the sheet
- ETHERNET2 - RMII
- PF6
- PF7
- ETH2
- PF4
- PE2
- PG11
- PA12
- (near R36) PG5
- PB2
- PG15
- MCP_IO10
- PG8

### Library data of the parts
C28 C30 C32 C33 C35 C37 = MCD-00006: as C71 on sheet Ethernet1_RMII
C38 = MCD-00724: as C90 on sheet Ethernet1_RMII
C39 = MCD-00099: as C91 on sheet Ethernet1_RMII
C40 = MCD-02377: as C92 on sheet Ethernet1_RMII
CN15 = MCD-02475: as CN4 on sheet Ethernet1_RMII
L4 = MCD-00047: as L5 on sheet Ethernet1_RMII
R24 R29 R32 R38 R43 R48 = MCD-00053: as R70 on sheet Ethernet1_RMII
R25 R26 = MCD-00053: as R69 on sheet Ethernet1_RMII
R27 R52 = MCD-00441: as R76 on sheet Ethernet1_RMII
R28 = MCD-00052: as R77 on sheet Ethernet1_RMII
R30 = MCD-00052: as R104 on sheet Ethernet1_RMII
R31 = MCD-00068: as R80 on sheet Ethernet1_RMII
R36 R41 R51 = MCD-00455: as R79 on sheet Ethernet1_RMII
R37 R39 R40 R42 = MCD-00565: as R92 on sheet Ethernet1_RMII
R47 = MCD-00723: as R101 on sheet Ethernet1_RMII
R50 = MCD-00189: as R107 on sheet Ethernet1_RMII
U7 = MCD-00719: as U13 on sheet Ethernet1_RMII
U8 = MCD-00250: as U15 on sheet Ethernet1_RMII

## Sheet Power_MPU.SchDoc: STM32 MPU power
size A3; Date: Not used; ApprovedBy: Not used; CheckedBy: Not used; Author: Not used; CompanyName: STMicroelectronics; DrawnBy: Not used; Engineer: Not used; Organization: Not used; Address1: Not used; Address2: Not used; Address3: Not used; Address4: Not used; DocumentNumber: 4; Revision: Not used; SheetNumber: 4; SheetTotal: 17
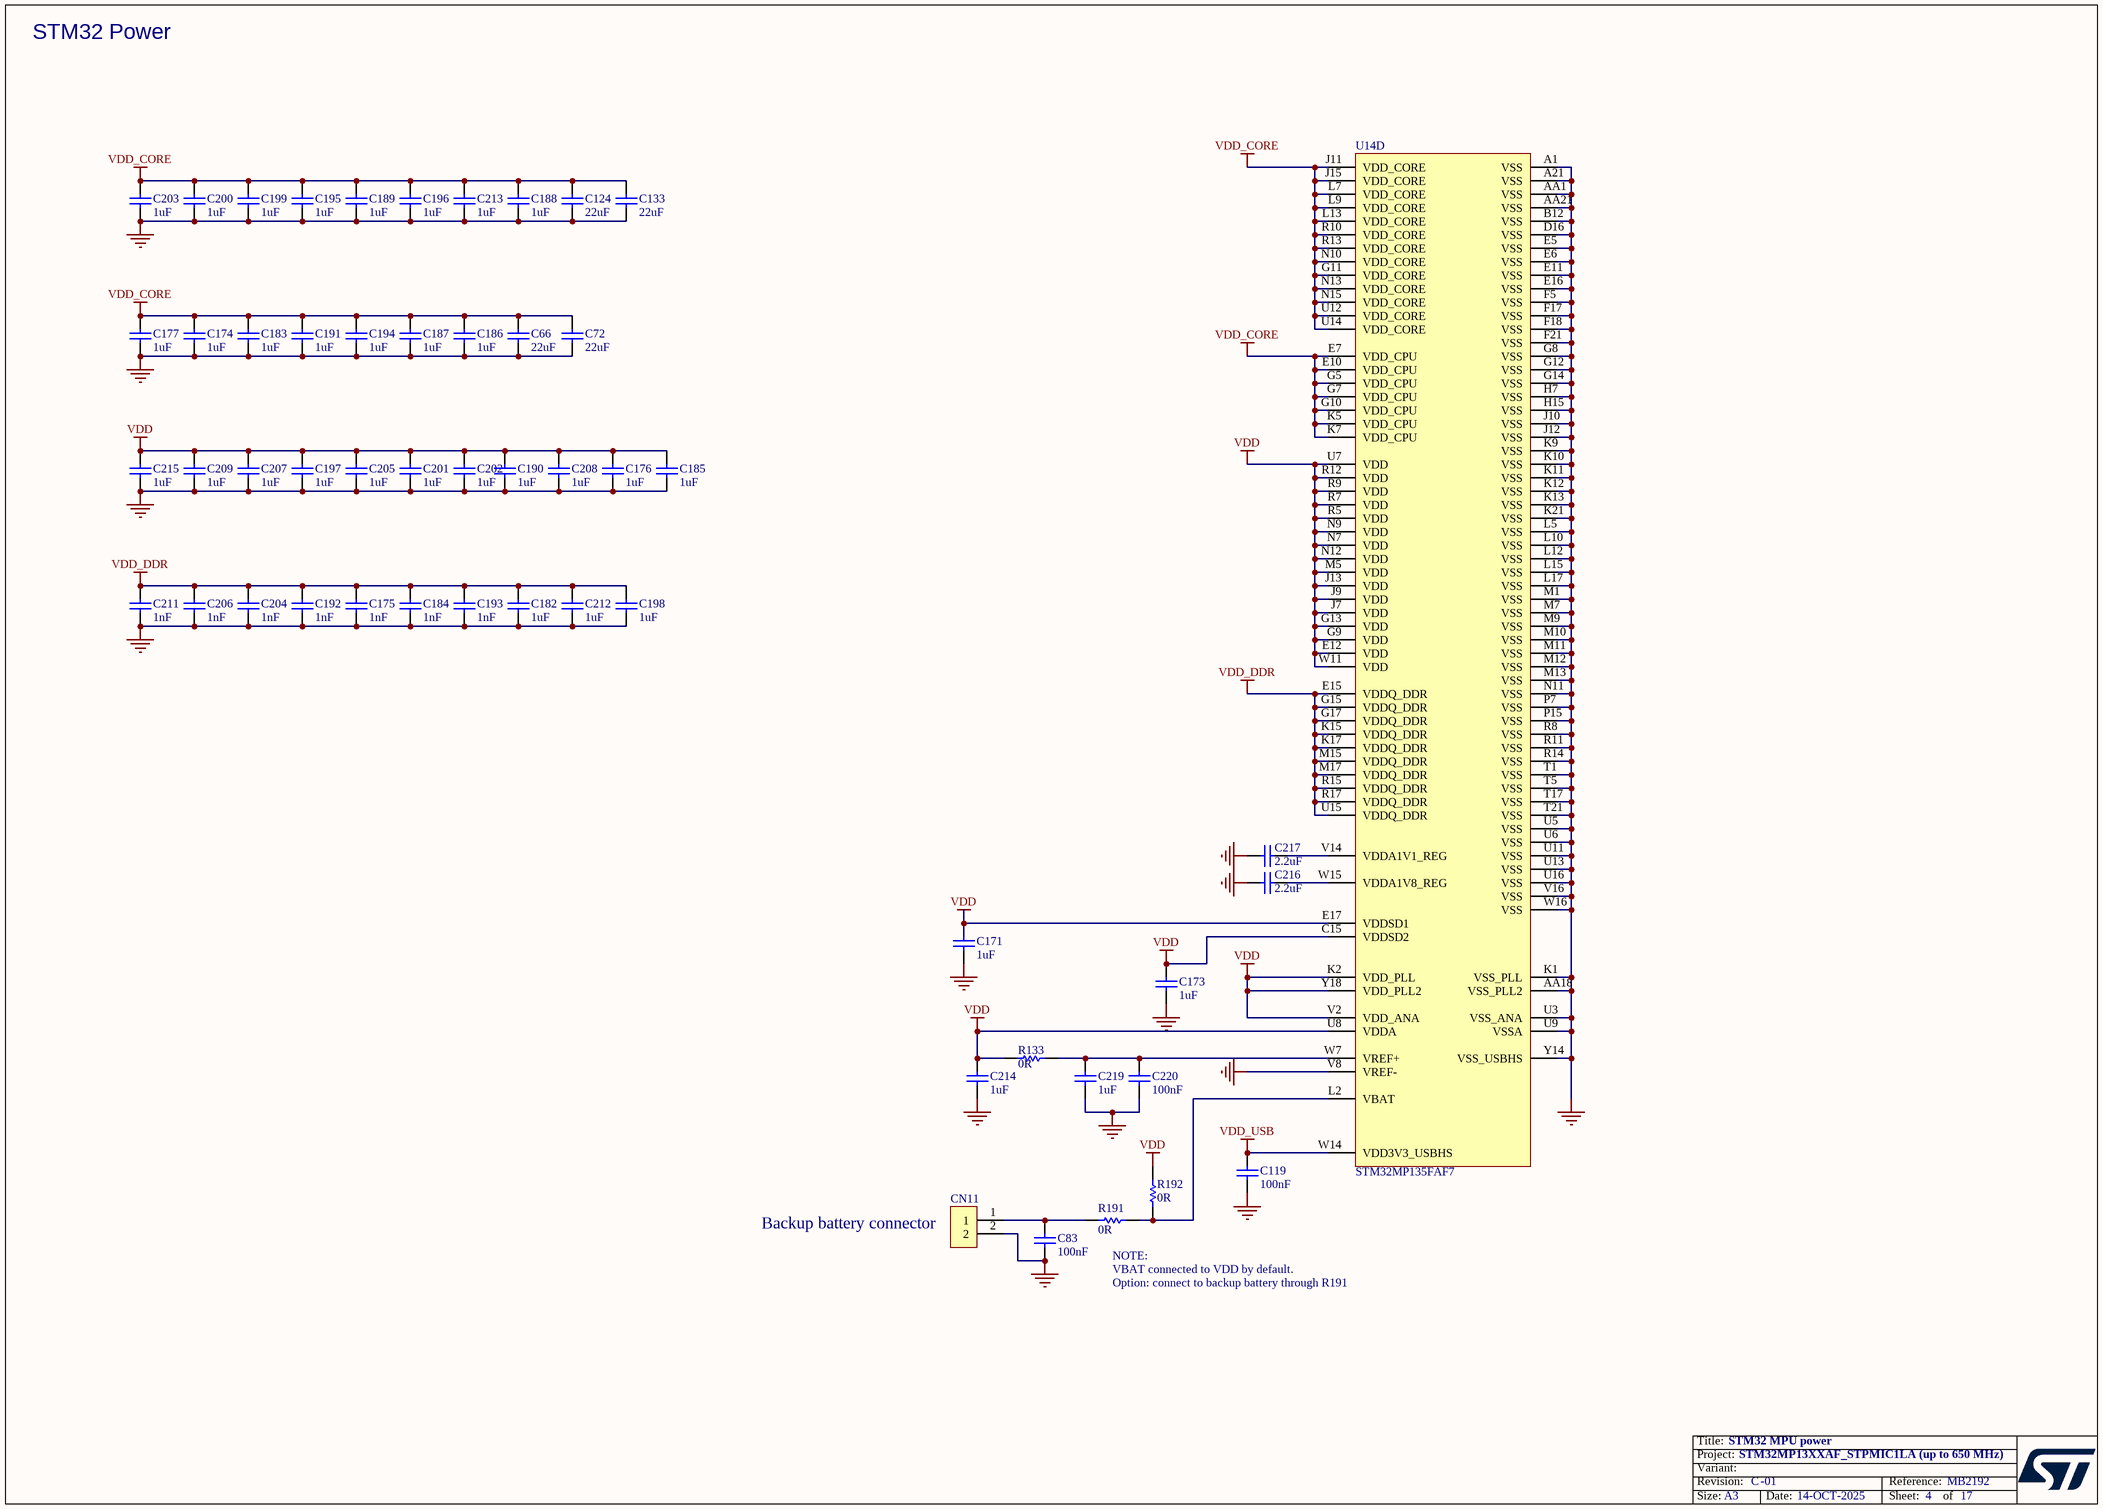
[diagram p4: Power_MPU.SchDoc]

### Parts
C66  value 22uF  [C0603]  (hidden comment: Capacitor)
C72  value 22uF  [C0603]  (hidden comment: Capacitor)
C83  value 100nF  [C0402]  (hidden comment: Capacitor)
C119  value 100nF  [C0402]  (hidden comment: Capacitor)
C124  value 22uF  [C0603]  (hidden comment: Capacitor)
C133  value 22uF  [C0603]  (hidden comment: Capacitor)
C171  value 1uF  [C0201_MURATA_GRM033_H0P3]  (hidden comment: Capacitor)
C173  value 1uF  [C0201_MURATA_GRM033_H0P3]  (hidden comment: Capacitor)
C174  value 1uF  [C0201_MURATA_GRM033_H0P3]  (hidden comment: Capacitor)
C175  value 1nF  [C0201_MURATA_GRM033_H0P3]  (hidden comment: Capacitor)
C176  value 1uF  [C0201_MURATA_GRM033_H0P3]  (hidden comment: Capacitor)
C177  value 1uF  [C0201_MURATA_GRM033_H0P3]  (hidden comment: Capacitor)
C182  value 1uF  [C0201_MURATA_GRM033_H0P3]  (hidden comment: Capacitor)
C183  value 1uF  [C0201_MURATA_GRM033_H0P3]  (hidden comment: Capacitor)
C184  value 1nF  [C0201_MURATA_GRM033_H0P3]  (hidden comment: Capacitor)
C185  value 1uF  [C0201_MURATA_GRM033_H0P3]  (hidden comment: Capacitor)
C186  value 1uF  [C0201_MURATA_GRM033_H0P3]  (hidden comment: Capacitor)
C187  value 1uF  [C0201_MURATA_GRM033_H0P3]  (hidden comment: Capacitor)
C188  value 1uF  [C0201_MURATA_GRM033_H0P3]  (hidden comment: Capacitor)
C189  value 1uF  [C0201_MURATA_GRM033_H0P3]  (hidden comment: Capacitor)
C190  value 1uF  [C0201_MURATA_GRM033_H0P3]  (hidden comment: Capacitor)
C191  value 1uF  [C0201_MURATA_GRM033_H0P3]  (hidden comment: Capacitor)
C192  value 1nF  [C0201_MURATA_GRM033_H0P3]  (hidden comment: Capacitor)
C193  value 1nF  [C0201_MURATA_GRM033_H0P3]  (hidden comment: Capacitor)
C194  value 1uF  [C0201_MURATA_GRM033_H0P3]  (hidden comment: Capacitor)
C195  value 1uF  [C0201_MURATA_GRM033_H0P3]  (hidden comment: Capacitor)
C196  value 1uF  [C0201_MURATA_GRM033_H0P3]  (hidden comment: Capacitor)
C197  value 1uF  [C0201_MURATA_GRM033_H0P3]  (hidden comment: Capacitor)
C198  value 1uF  [C0201_MURATA_GRM033_H0P3]  (hidden comment: Capacitor)
C199  value 1uF  [C0201_MURATA_GRM033_H0P3]  (hidden comment: Capacitor)
C200  value 1uF  [C0201_MURATA_GRM033_H0P3]  (hidden comment: Capacitor)
C201  value 1uF  [C0201_MURATA_GRM033_H0P3]  (hidden comment: Capacitor)
C202  value 1uF  [C0201_MURATA_GRM033_H0P3]  (hidden comment: Capacitor)
C203  value 1uF  [C0201_MURATA_GRM033_H0P3]  (hidden comment: Capacitor)
C204  value 1nF  [C0201_MURATA_GRM033_H0P3]  (hidden comment: Capacitor)
C205  value 1uF  [C0201_MURATA_GRM033_H0P3]  (hidden comment: Capacitor)
C206  value 1nF  [C0201_MURATA_GRM033_H0P3]  (hidden comment: Capacitor)
C207  value 1uF  [C0201_MURATA_GRM033_H0P3]  (hidden comment: Capacitor)
C208  value 1uF  [C0201_MURATA_GRM033_H0P3]  (hidden comment: Capacitor)
C209  value 1uF  [C0201_MURATA_GRM033_H0P3]  (hidden comment: Capacitor)
C211  value 1nF  [C0201_MURATA_GRM033_H0P3]  (hidden comment: Capacitor)
C212  value 1uF  [C0201_MURATA_GRM033_H0P3]  (hidden comment: Capacitor)
C213  value 1uF  [C0201_MURATA_GRM033_H0P3]  (hidden comment: Capacitor)
C214  value 1uF  [C0201_MURATA_GRM033_H0P3]  (hidden comment: Capacitor)
C215  value 1uF  [C0201_MURATA_GRM033_H0P3]  (hidden comment: Capacitor)
C216  value 2.2uF  [C0201_H0P5]  (hidden comment: Capacitor)
C217  value 2.2uF  [C0201_H0P5]  (hidden comment: Capacitor)
C219  value 1uF  [C0201_MURATA_GRM033_H0P3]  (hidden comment: Capacitor)
C220  value 100nF  [C0402]  (hidden comment: Capacitor)
CN11  Header 2x1  [CON_MOLEX_53047-0210]  (value not drawn)
R133  value 0R  [R0402]  (hidden comment: Resistor)
R191  value 0R  [R0402]  (hidden comment: Resistor)
R192  value 0R  [R0402]  (hidden comment: Resistor)
U14  STM32MP135FAF7  [ICC_TFBGA320_11X11_STM32MP135FA7_P050_H1P20]  (part D of 5)

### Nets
GND: C66.1 C72.1 C83.1 C119.1 C124.1 C133.1 C171.1 C173.1 C174.1 C175.1 C176.1 C177.2 C182.1 C183.1 C184.1 C185.2 C186.1 C187.1 C188.1 C189.1 C190.1 C191.2 C192.1 C193.1 C194.1 C195.2 C196.1 C197.1 C198.1 C199.1 C200.1 C201.1 C202.1 C203.2 C204.2 C205.1 C206.1 C207.2 C208.1 C209.1 C211.1 C212.1 C213.1 C214.2 C215.2 C216.2 C217.2 C219.2 C220.1 CN11.2 U14.A1(VSS) U14.A21(VSS) U14.AA1(VSS) U14.AA18(VSS_PLL2) U14.AA21(VSS) U14.B12(VSS) U14.D16(VSS) U14.E5(VSS) U14.E6(VSS) U14.E11(VSS) U14.E16(VSS) U14.F5(VSS) U14.F17(VSS) U14.F18(VSS) U14.F21(VSS) U14.G8(VSS) U14.G12(VSS) U14.G14(VSS) U14.H7(VSS) U14.H15(VSS) U14.J10(VSS) U14.J12(VSS) U14.K1(VSS_PLL) U14.K9(VSS) U14.K10(VSS) U14.K11(VSS) U14.K12(VSS) U14.K13(VSS) U14.K21(VSS) U14.L5(VSS) U14.L10(VSS) U14.L12(VSS) U14.L15(VSS) U14.L17(VSS) U14.M1(VSS) U14.M7(VSS) U14.M9(VSS) U14.M10(VSS) U14.M11(VSS) U14.M12(VSS) U14.M13(VSS) U14.N11(VSS) U14.P7(VSS) U14.P15(VSS) U14.R8(VSS) U14.R11(VSS) U14.R14(VSS) U14.T1(VSS) U14.T5(VSS) U14.T17(VSS) U14.T21(VSS) U14.U3(VSS_ANA) U14.U5(VSS) U14.U6(VSS) U14.U9(VSSA) U14.U11(VSS) U14.U13(VSS) U14.U16(VSS) U14.V8(VREF-) U14.V16(VSS) U14.W16(VSS) U14.Y14(VSS_USBHS)
VDD: C171.2 C173.2 C176.2 C185.1 C190.2 C197.2 C201.2 C202.2 C205.2 C207.1 C208.2 C209.2 C214.1 C215.1 R133.2 R192.2 U14.C15(VDDSD2) U14.E12(VDD) U14.E17(VDDSD1) U14.G9(VDD) U14.G13(VDD) U14.J7(VDD) U14.J9(VDD) U14.J13(VDD) U14.K2(VDD_PLL) U14.M5(VDD) U14.N7(VDD) U14.N9(VDD) U14.N12(VDD) U14.R5(VDD) U14.R7(VDD) U14.R9(VDD) U14.R12(VDD) U14.U7(VDD) U14.U8(VDDA) U14.V2(VDD_ANA) U14.W11(VDD) U14.Y18(VDD_PLL2)
VDD_CORE: C66.2 C72.2 C124.2 C133.2 C174.2 C177.1 C183.2 C186.2 C187.2 C188.2 C189.2 C191.1 C194.2 C195.1 C196.2 C199.2 C200.2 C203.1 C213.2 U14.E7(VDD_CPU) U14.E10(VDD_CPU) U14.G5(VDD_CPU) U14.G7(VDD_CPU) U14.G10(VDD_CPU) U14.G11(VDD_CORE) U14.J11(VDD_CORE) U14.J15(VDD_CORE) U14.K5(VDD_CPU) U14.K7(VDD_CPU) U14.L7(VDD_CORE) U14.L9(VDD_CORE) U14.L13(VDD_CORE) U14.N10(VDD_CORE) U14.N13(VDD_CORE) U14.N15(VDD_CORE) U14.R10(VDD_CORE) U14.R13(VDD_CORE) U14.U12(VDD_CORE) U14.U14(VDD_CORE)
VDD_DDR: C175.2 C182.2 C184.2 C192.2 C193.2 C198.2 C204.1 C206.2 C211.2 C212.2 U14.E15(VDDQ_DDR) U14.G15(VDDQ_DDR) U14.G17(VDDQ_DDR) U14.K15(VDDQ_DDR) U14.K17(VDDQ_DDR) U14.M15(VDDQ_DDR) U14.M17(VDDQ_DDR) U14.R15(VDDQ_DDR) U14.R17(VDDQ_DDR) U14.U15(VDDQ_DDR)
VDD_USB: C119.2 U14.W14(VDD3V3_USBHS)
NetC83_2: C83.2 CN11.1 R191.2
NetC216_1: C216.1 U14.W15(VDDA1V8_REG)
NetC217_1: C217.1 U14.V14(VDDA1V1_REG)
NetC219_1: C219.1 C220.2 R133.1 U14.W7(VREF+)
NetR191_1: R191.1 R192.1 U14.L2(VBAT)

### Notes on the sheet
- STM32 Power
- (near CN11) Backup battery connector
- NOTE:
  VBAT connected to VDD by default.
  Option: connect to backup battery through R191

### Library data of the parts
C66 C72 C124 C133 = MCD-00100: Capacitor, MLCC, 22uF, 6V3, X5R, +/-20%, 0603, T=0.8mm; Part_Preference: Recommended; Manufacturer: MURATA; Manufacturer_Part_Number: GRM188R60J226MEA0; Partial_Alternate_Internal_Part_Number: MCD-04184; Component_Country_Of_Origin: Japan°°; ShowFields: YES; ID: 2766
C83 C119 C220 = MCD-00006: as C71 on sheet Ethernet1_RMII
C171 C173 C174 C176 C177 C182 C183 C185-C191 C194-C203 C205 C207-C209 C212-C215 C219 = MCD-02377: Capacitor, MLCC, 1uF, 6.3V, X5R, +/-20%, 0201, T=0,3mm; Part_Preference: Recommended; Manufacturer: MURATA; Manufacturer_Part_Number: GRM033R60J105MEA2; Partial_Alternate_Internal_Part_Number: MCD-04356; Order_Code_RS: 820-0643; Component_Country_Of_Origin: Japan°; ShowFields: YES; ID: 4483
C175 C184 C192 C193 C204 C206 C211 = MCD-01729: Capacitor, MLCC, 1nF, 25V, X7R,+/-5%, 0201,T=0.3mm; Part_Preference: Recommended; Manufacturer: MURATA; Manufacturer_Part_Number: GRM033R71E102JA01; Order_Code_RS: 185-1954; Component_Country_Of_Origin: Japan°°; ShowFields: YES; ID: 3829
C216 C217 = MCD-02235: Capacitor, MLCC, 2.2uF, 10V, X5R,+/-10%, 0201, T=0.5mm; Manufacturer_Part_Number: GRM033R61A225KE47; Manufacturer: MURATA; Part_Preference: Recommended; Order_Code_RS: NA; Component_Country_Of_Origin: Japan°°; ShowFields: YES; ID: 4335
CN11 = MCD-00655: Header, 2x1, 1.25mm, VR, TH, T=2.25mm/2.3mm; Part_Type: Connector; Manufacturer_Part_Number: 53047-0210; Manufacturer: MOLEX; BMS_Part_Number: 9083002; Part_Preference: Recommended; Partial_Alternate_Internal_Part_Number: MCD-04371, MCD-04208; Value: Shrouded_53047-0210; Order_Code_RS: 279-9213; Component_Country_Of_Origin: Unknown; ShowFields: YES; ID: 3091
R133 R191 R192 = MCD-00052: as R104 on sheet Ethernet1_RMII
U14 = MCD-02251: Cortex-A7 @ 900MHz, 128KB-ROM, 128KB-SRAM, 2x Ethernet, 2x ADC, 2x CAN FD, TSC, Camera, Display, Secure Boot, Cryptography, DRAM enc/dec, PKA; Part_Preference: Recommended; Part_Type: IC; Manufacturer: STMICROELECTRONICS; Manufacturer_HQ_COO: EU; Component_Country_Of_Origin: Unknown; ShowFields: YES; ID: 4351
